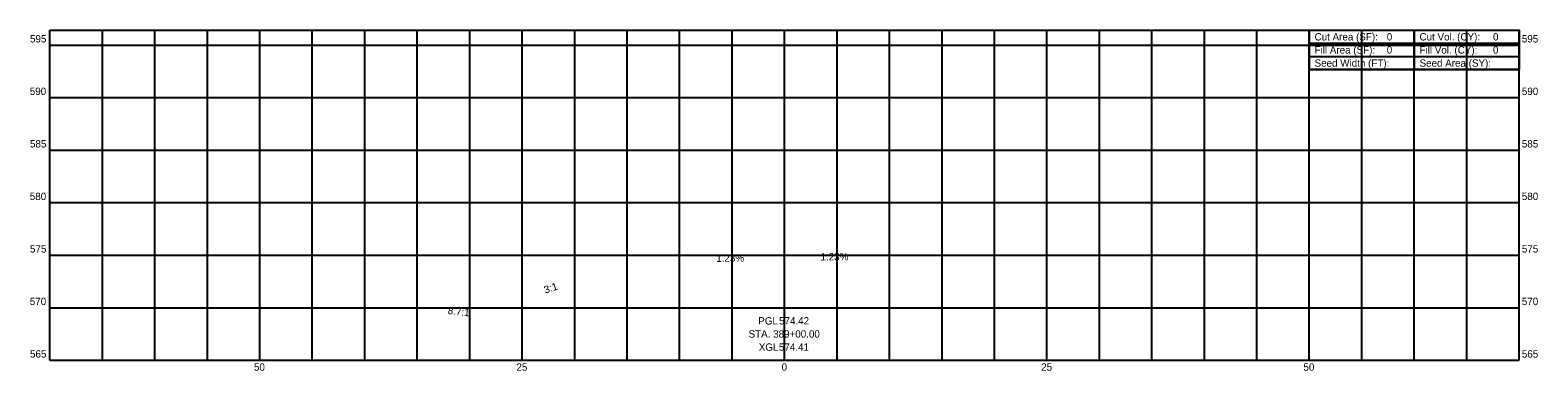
# Model space of a CAD drawing. Extents: x -72 to 72, y 564 to 596.
import ezdxf

# ---------------------------------------------------------------- set-up
doc = ezdxf.new("R2010")
doc.units = 0
for name, color, linetype in [('Default', 7, 'Continuous'), ('SH_Data', 7, 'Continuous'), ('SH_Major_Grid_Line', 7, 'Continuous'), ('SH_Masking', 7, 'Continuous'), ('SH_Text', 7, 'Continuous')]:
    doc.layers.add(name, color=color, linetype=linetype)

msp = doc.modelspace()

# ---------------------------------------------------------------- linework, layer by layer
at = {"layer": 'Default'}
msp.add_circle((70, 596.42), 0.000417, dxfattribs=at)
msp.add_circle((70, 596.42), 0.000417, dxfattribs=at)
msp.add_circle((70, 596.42), 0.000417, dxfattribs=at)
msp.add_circle((70, 596.42), 0.000417, dxfattribs=at)
msp.add_circle((70, 596.42), 0.000417, dxfattribs=at)
msp.add_circle((70, 596.42), 0.000417, dxfattribs=at)
msp.add_circle((70, 596.42), 0.000417, dxfattribs=at)
msp.add_circle((70, 596.42), 0.000417, dxfattribs=at)
msp.add_circle((70, 596.42), 0.000417, dxfattribs=at)
msp.add_circle((70, 596.42), 0.000417, dxfattribs=at)
msp.add_circle((70, 596.42), 0.000417, dxfattribs=at)
msp.add_circle((70, 596.42), 0.000417, dxfattribs=at)
at = {"layer": 'SH_Data'}
for p, q in [((50, 596.42), (70, 596.42)), ((50, 596.42), (50, 593.92)), ((60, 596.42), (60, 592.67)), ((70, 596.42), (70, 593.92)), ((50, 595.17), (70, 595.17)), ((50, 593.92), (70, 593.92)), ((58.3, 593.29), (58.3, 593.29)), ((67.95, 593.29), (67.95, 593.29))]:
    msp.add_line(p, q, dxfattribs=at)
msp.add_lwpolyline([(50, 593.92), (50, 592.67), (70, 592.67), (70, 593.92)], dxfattribs=at)
at = {"layer": 'SH_Major_Grid_Line'}
for p, q in [((-70, 596.42), (70, 596.42)), ((-70, 565), (-70, 596.42)), ((-65, 565), (-65, 596.42)), ((-60, 565), (-60, 596.42)), ((-55, 565), (-55, 596.42)), ((-50, 565), (-50, 596.42)), ((-45, 565), (-45, 596.42)), ((-40, 565), (-40, 596.42)), ((-35, 565), (-35, 596.42)), ((-30, 565), (-30, 596.42)), ((-25, 565), (-25, 596.42)), ((-20, 565), (-20, 596.42)), ((-15, 565), (-15, 596.42)), ((-10, 565), (-10, 596.42)), ((-5, 565), (-5, 596.42)), ((0, 565), (0, 596.42)), ((5, 565), (5, 596.42)), ((10, 565), (10, 596.42)), ((15, 565), (15, 596.42)), ((20, 565), (20, 596.42)), ((25, 565), (25, 596.42)), ((30, 565), (30, 596.42)), ((35, 565), (35, 596.42)), ((40, 565), (40, 596.42)), ((45, 565), (45, 596.42)), ((50, 565), (50, 596.42)), ((55, 565), (55, 596.42)), ((60, 565), (60, 596.42)), ((65, 565), (65, 596.42)), ((70, 565), (70, 596.42)), ((-70, 595), (70, 595)), ((-70, 590), (70, 590)), ((-70, 585), (70, 585)), ((-70, 580), (70, 580)), ((-70, 575), (70, 575)), ((-70, 570), (70, 570)), ((-70, 565), (70, 565))]:
    msp.add_line(p, q, dxfattribs=at)
at = {"layer": 'SH_Masking'}
msp.add_lwpolyline([(50, 596.42), (70, 596.42), (70, 592.67), (50, 592.67)], close=True, dxfattribs=at)

# ---------------------------------------------------------------- texts
at = {"layer": 'SH_Text'}
for s, p in [('595', (-71.9, 595.25)), ('Cut Area (SF):', (50.5, 595.44)), ('Fill Area (SF):', (50.5, 594.19)), ('0', (57.38, 595.44)), ('0', (57.38, 594.19)), ('Cut Vol. (CY):', (60.5, 595.44)), ('Fill Vol. (CY):', (60.5, 594.19)), ('0', (67.5, 595.44)), ('0', (67.5, 594.19)), ('595', (70.25, 595.25)), ('Seed Width (FT):', (50.5, 592.94)), ('Seed Area (SY):', (60.5, 592.94)), ('590', (-71.92, 590.25)), ('590', (70.25, 590.25)), ('585', (-71.9, 585.25)), ('585', (70.25, 585.25)), ('580', (-71.92, 580.25)), ('580', (70.25, 580.25)), ('575', (-71.9, 575.25)), ('575', (70.25, 575.25)), ('570', (-71.92, 570.25)), ('570', (70.25, 570.25)), ('PGL ', (-2.51, 568.4)), ('574.42', (-0.53, 568.4)), ('STA. 389+00.00', (-3.43, 567.15)), ('XGL ', (-2.46, 565.9)), ('574.41', (-0.54, 565.9)), ('565', (-71.9, 565.25)), ('50', (-50.56, 564)), ('25', (-25.55, 564)), ('0', (-0.28, 564)), ('25', (24.45, 564)), ('50', (49.44, 564)), ('565', (70.25, 565.25))]:
    msp.add_text(s, height=0.7, dxfattribs=at).set_placement(p)
for s, rotation, p in [('1.23%', 0.7032, (-6.51, 574.36)), ('1.23%', 0.7032, (3.43, 574.49)), ('3:1', 18.5322, (-22.79, 571.34)), ('8.7:1', 353.4592, (-32.12, 569.4))]:
    msp.add_text(s, height=0.7, rotation=rotation, dxfattribs=at).set_placement(p)

doc.saveas('drawing.dxf')
